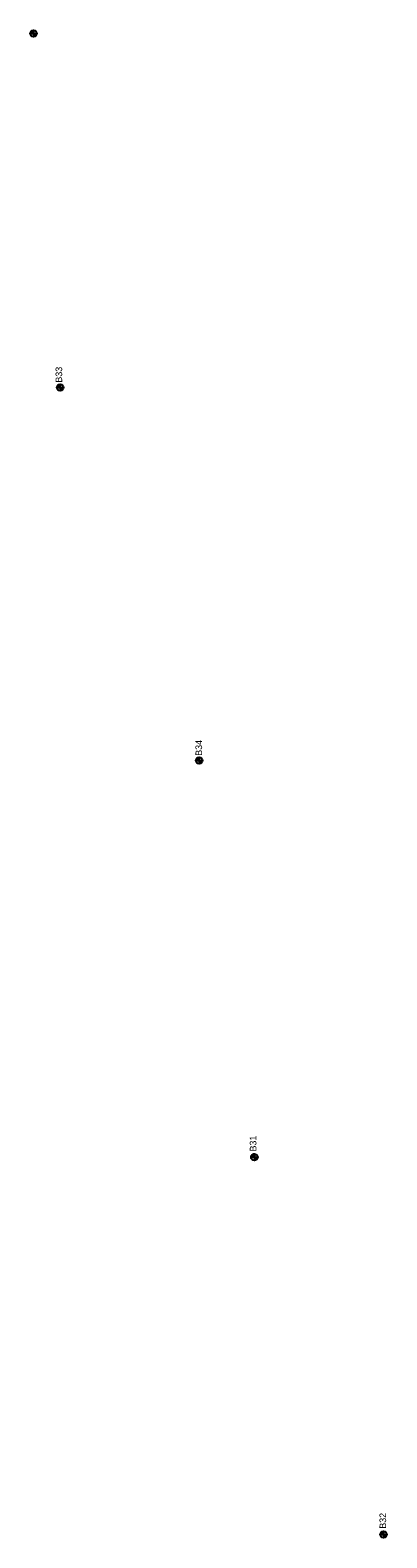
# Model space of a CAD drawing. Extents: x 327762 to 372792, y 127949 to 259367.
# Drawn here: x 361411 to 361949, y 145719 to 147993 of the extents above; entities that cross this region are included whole.
import ezdxf

# ---------------------------------------------------------------- set-up
doc = ezdxf.new("R2010")
doc.units = 0
for name, color, linetype in [('E_SOIL_BORE1 [KAPUR_CADDS_LEVELS]', 7, 'Continuous'), ('E_SOIL_BORE2 [KAPUR_CADDS_LEVELS]', 7, 'Continuous'), ('P_MARK', 7, 'Continuous')]:
    doc.layers.add(name, color=color, linetype=linetype)

msp = doc.modelspace()

# ---------------------------------------------------------------- linework, layer by layer
at = {"layer": 'P_MARK'}
for p, q in [((361410.8, 147987.9), (361420.8, 147987.9)), ((361415.8, 147992.9), (361415.8, 147982.9)), ((361456, 147459.1), (361456, 147449.1)), ((361451, 147454.1), (361461, 147454.1)), ((361660.8, 146891.4), (361670.8, 146891.4)), ((361665.8, 146896.4), (361665.8, 146886.4)), ((361748.9, 146298.4), (361748.9, 146288.4)), ((361743.9, 146293.4), (361753.9, 146293.4)), ((361943.7, 145729.1), (361943.7, 145719.1)), ((361938.7, 145724.1), (361948.7, 145724.1))]:
    msp.add_line(p, q, dxfattribs=at)
for centre in [(361415.8, 147987.9), (361456, 147454.1), (361665.8, 146891.4), (361748.9, 146293.4), (361943.7, 145724.1)]:
    msp.add_circle(centre, 5, dxfattribs=at)
for centre, radius, start, end in [((361415.8, 147987.9), 4.5, 89.9869, 179.9869), ((361415.8, 147987.9), 4, 89.9869, 179.9869), ((361415.8, 147987.9), 3.5, 89.9869, 179.9869), ((361415.8, 147987.9), 3, 89.9869, 179.9869), ((361415.8, 147987.9), 2.5, 89.9869, 179.9869), ((361415.8, 147987.9), 2, 89.9869, 179.9869), ((361415.8, 147987.9), 1.5, 89.9869, 179.9869), ((361415.8, 147987.9), 1, 89.9869, 179.9869), ((361415.8, 147987.9), 0.5, 89.9869, 179.9869), ((361415.8, 147987.9), 4.5, 269.9869, 359.9869), ((361415.8, 147987.9), 4, 269.9869, 359.9869), ((361415.8, 147987.9), 3.5, 269.9869, 359.9869), ((361415.8, 147987.9), 3, 269.9869, 359.9869), ((361415.8, 147987.9), 2.5, 269.9869, 359.9869), ((361415.8, 147987.9), 2, 269.9869, 359.9869), ((361415.8, 147987.9), 1.5, 269.9869, 359.9869), ((361415.8, 147987.9), 1, 269.9869, 359.9869), ((361415.8, 147987.9), 0.5, 269.9869, 359.9869), ((361456, 147454.1), 4.5, 89.9869, 179.9869), ((361456, 147454.1), 4, 89.9869, 179.9869), ((361456, 147454.1), 3.5, 89.9869, 179.9869), ((361456, 147454.1), 3, 89.9869, 179.9869), ((361456, 147454.1), 2.5, 89.9869, 179.9869), ((361456, 147454.1), 2, 89.9869, 179.9869), ((361456, 147454.1), 1.5, 89.9869, 179.9869), ((361456, 147454.1), 1, 89.9869, 179.9869), ((361456, 147454.1), 0.5, 89.9869, 179.9869), ((361456, 147454.1), 4.5, 269.9869, 359.9869), ((361456, 147454.1), 4, 269.9869, 359.9869), ((361456, 147454.1), 3.5, 269.9869, 359.9869), ((361456, 147454.1), 3, 269.9869, 359.9869), ((361456, 147454.1), 2.5, 269.9869, 359.9869), ((361456, 147454.1), 2, 269.9869, 359.9869), ((361456, 147454.1), 1.5, 269.9869, 359.9869), ((361456, 147454.1), 1, 269.9869, 359.9869), ((361456, 147454.1), 0.5, 269.9869, 359.9869), ((361665.8, 146891.4), 4.5, 89.9869, 179.9869), ((361665.8, 146891.4), 4, 89.9869, 179.9869), ((361665.8, 146891.4), 3.5, 89.9869, 179.9869), ((361665.8, 146891.4), 3, 89.9869, 179.9869), ((361665.8, 146891.4), 2.5, 89.9869, 179.9869), ((361665.8, 146891.4), 2, 89.9869, 179.9869), ((361665.8, 146891.4), 1.5, 89.9869, 179.9869), ((361665.8, 146891.4), 1, 89.9869, 179.9869), ((361665.8, 146891.4), 0.5, 89.9869, 179.9869), ((361665.8, 146891.4), 4.5, 269.9869, 359.9869), ((361665.8, 146891.4), 4, 269.9869, 359.9869), ((361665.8, 146891.4), 3.5, 269.9869, 359.9869), ((361665.8, 146891.4), 3, 269.9869, 359.9869), ((361665.8, 146891.4), 2.5, 269.9869, 359.9869), ((361665.8, 146891.4), 2, 269.9869, 359.9869), ((361665.8, 146891.4), 1.5, 269.9869, 359.9869), ((361665.8, 146891.4), 1, 269.9869, 359.9869), ((361665.8, 146891.4), 0.5, 269.9869, 359.9869), ((361748.9, 146293.4), 4.5, 89.9869, 179.9869), ((361748.9, 146293.4), 4, 89.9869, 179.9869), ((361748.9, 146293.4), 3.5, 89.9869, 179.9869), ((361748.9, 146293.4), 3, 89.9869, 179.9869), ((361748.9, 146293.4), 2.5, 89.9869, 179.9869), ((361748.9, 146293.4), 2, 89.9869, 179.9869), ((361748.9, 146293.4), 1.5, 89.9869, 179.9869), ((361748.9, 146293.4), 1, 89.9869, 179.9869), ((361748.9, 146293.4), 0.5, 89.9869, 179.9869), ((361748.9, 146293.4), 4.5, 269.9869, 359.9869), ((361748.9, 146293.4), 4, 269.9869, 359.9869), ((361748.9, 146293.4), 3.5, 269.9869, 359.9869), ((361748.9, 146293.4), 3, 269.9869, 359.9869), ((361748.9, 146293.4), 2.5, 269.9869, 359.9869), ((361748.9, 146293.4), 2, 269.9869, 359.9869), ((361748.9, 146293.4), 1.5, 269.9869, 359.9869), ((361748.9, 146293.4), 1, 269.9869, 359.9869), ((361748.9, 146293.4), 0.5, 269.9869, 359.9869), ((361943.7, 145724.1), 4.5, 89.9869, 179.9869), ((361943.7, 145724.1), 4, 89.9869, 179.9869), ((361943.7, 145724.1), 3.5, 89.9869, 179.9869), ((361943.7, 145724.1), 3, 89.9869, 179.9869), ((361943.7, 145724.1), 2.5, 89.9869, 179.9869), ((361943.7, 145724.1), 2, 89.9869, 179.9869), ((361943.7, 145724.1), 1.5, 89.9869, 179.9869), ((361943.7, 145724.1), 1, 89.9869, 179.9869), ((361943.7, 145724.1), 0.5, 89.9869, 179.9869), ((361943.7, 145724.1), 4.5, 269.9869, 359.9869), ((361943.7, 145724.1), 4, 269.9869, 359.9869), ((361943.7, 145724.1), 3.5, 269.9869, 359.9869), ((361943.7, 145724.1), 3, 269.9869, 359.9869), ((361943.7, 145724.1), 2.5, 269.9869, 359.9869), ((361943.7, 145724.1), 2, 269.9869, 359.9869), ((361943.7, 145724.1), 1.5, 269.9869, 359.9869), ((361943.7, 145724.1), 1, 269.9869, 359.9869), ((361943.7, 145724.1), 0.5, 269.9869, 359.9869)]:
    msp.add_arc(centre, radius, start, end, dxfattribs=at)

# ---------------------------------------------------------------- texts
at = {"layer": 'E_SOIL_BORE1 [KAPUR_CADDS_LEVELS]'}
for s, p in [('B33', (361459.1, 147461.4)), ('B34', (361670.1, 146898.6))]:
    msp.add_text(s, height=10, rotation=89.9869, dxfattribs=at).set_placement(p)
at = {"layer": 'E_SOIL_BORE2 [KAPUR_CADDS_LEVELS]'}
for s, p in [('B31', (361752, 146301.8)), ('B32', (361947.6, 145732.9))]:
    msp.add_text(s, height=10, rotation=89.9869, dxfattribs=at).set_placement(p)

doc.saveas('drawing.dxf')
